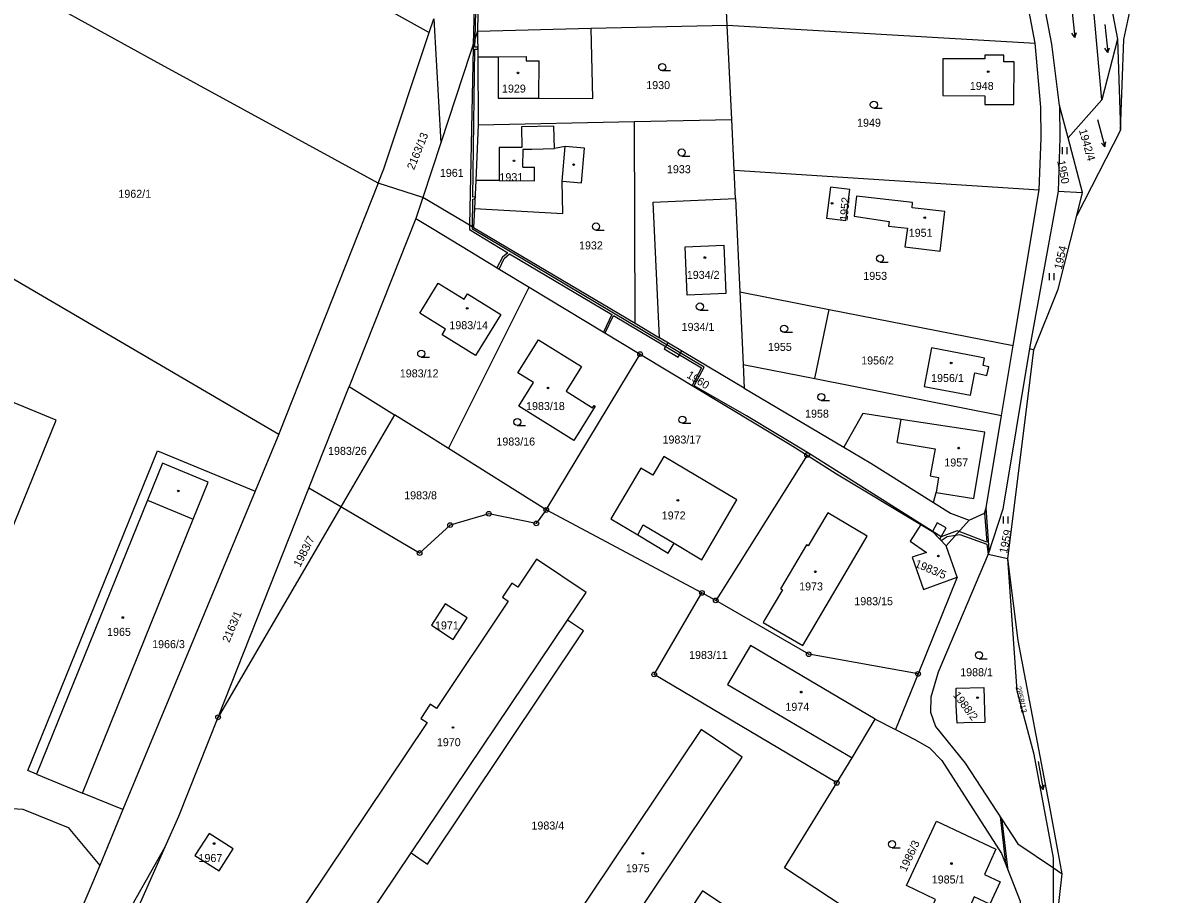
# Model space of a CAD drawing. Extents: x -562167 to -556918, y -1077891 to -1070763.
# Drawn here: x -560372.7 to -560130, y -1077028.4 to -1076843.2 of the extents above; entities that cross this region are included whole.
import ezdxf

# ---------------------------------------------------------------- set-up
doc = ezdxf.new("R2010")
doc.units = 0
for name, color, linetype in [('Hranice parcel', 7, 'Continuous'), ('Parcelní čísla', 7, 'Continuous'), ('Vnitřní kresba', 7, 'Continuous'), ('Věcná břemena k části', 7, 'Continuous'), ('Značky bodu BP', 7, 'Continuous'), ('Značky budov', 7, 'Continuous'), ('Značky kultur', 7, 'Continuous')]:
    doc.layers.add(name, color=color, linetype=linetype)

msp = doc.modelspace()

# ---------------------------------------------------------------- linework, layer by layer
at = {"layer": 'Hranice parcel'}
for p, q in [((-560358.76, -1076804.84), (-560286.39, -1076845.32)), ((-560138.79, -1076846.79), (-560130.01, -1076806.27)), ((-560157.61, -1076847.59), (-560163.26, -1076817.83)), ((-560275.77, -1076826.63), (-560276.1, -1076844.98)), ((-560223.06, -1076843.72), (-560223.82, -1076826.82)), ((-560143.58, -1076829.02), (-560140.13, -1076846.69)), ((-560286.39, -1076845.32), (-560285.41, -1076842.37)), ((-560285.41, -1076842.37), (-560283.95, -1076868.77)), ((-560276.1, -1076844.98), (-560251.98, -1076844.4)), ((-560251.98, -1076844.4), (-560223.06, -1076843.72)), ((-560223.06, -1076843.72), (-560157.61, -1076847.59)), ((-560222.12, -1076863.78), (-560223.06, -1076843.72)), ((-560276.1, -1076844.98), (-560283.95, -1076868.77)), ((-560276.1, -1076844.98), (-560276.06, -1076850.45)), ((-560140.13, -1076846.69), (-560143.47, -1076859.62)), ((-560140.13, -1076846.69), (-560139.49, -1076866.02)), ((-560139.49, -1076866.02), (-560138.79, -1076846.79)), ((-560276.06, -1076850.45), (-560275.96, -1076864.91)), ((-560150.64, -1076867.64), (-560152.43, -1076860.82)), ((-560150.64, -1076867.64), (-560143.47, -1076859.62)), ((-560242.76, -1076864.22), (-560222.12, -1076863.78)), ((-560221.61, -1076874.57), (-560222.12, -1076863.78)), ((-560275.96, -1076864.91), (-560276.49, -1076876.74)), ((-560275.96, -1076864.91), (-560242.76, -1076864.22)), ((-560242.66, -1076907.08), (-560242.76, -1076864.22)), ((-560139.49, -1076866.02), (-560148.79, -1076884.16)), ((-560283.95, -1076868.77), (-560287.76, -1076880.32)), ((-560147.57, -1076879.32), (-560150.64, -1076867.64)), ((-560221.61, -1076874.57), (-560156.75, -1076878.73)), ((-560221.32, -1076880.54), (-560221.61, -1076874.57)), ((-560287.76, -1076880.32), (-560297.22, -1076877.3)), ((-560276.49, -1076876.74), (-560276.76, -1076882.69)), ((-560404.42, -1076880.28), (-560318.34, -1076930.64)), ((-560287.76, -1076880.32), (-560289.24, -1076884.82)), ((-560276.95, -1076886.74), (-560287.76, -1076880.32)), ((-560221.32, -1076880.54), (-560220.39, -1076900.41)), ((-560162.28, -1076911.79), (-560156.75, -1076878.73)), ((-560152.76, -1076878.98), (-560158.84, -1076912.46)), ((-560152.76, -1076878.98), (-560147.57, -1076879.32)), ((-560148.79, -1076884.16), (-560147.57, -1076879.32)), ((-560276.76, -1076882.69), (-560276.95, -1076886.74)), ((-560289.24, -1076884.82), (-560303.38, -1076920.48)), ((-560276.95, -1076886.74), (-560242.66, -1076907.08)), ((-560282.32, -1076933.69), (-560265.13, -1076899.42)), ((-560265.13, -1076899.42), (-560241.57, -1076913.61)), ((-560220.39, -1076900.41), (-560201.37, -1076904.13)), ((-560220.39, -1076900.41), (-560219.67, -1076915.82)), ((-560204.45, -1076918.82), (-560201.37, -1076904.13)), ((-560201.37, -1076904.13), (-560162.28, -1076911.79)), ((-560242.66, -1076907.08), (-560237.45, -1076910.16)), ((-560219.44, -1076920.85), (-560237.45, -1076910.16)), ((-560164.75, -1076926.65), (-560162.28, -1076911.79)), ((-560158.84, -1076912.46), (-560157.89, -1076912.72)), ((-560261.53, -1076946.74), (-560241.57, -1076913.61)), ((-560159.06, -1076922), (-560157.89, -1076912.72)), ((-560219.67, -1076915.82), (-560219.44, -1076920.85)), ((-560219.67, -1076915.82), (-560204.45, -1076918.82)), ((-560204.45, -1076918.82), (-560164.75, -1076926.65)), ((-560311.95, -1076942.1), (-560303.38, -1076920.48)), ((-560303.38, -1076920.48), (-560293.79, -1076926.49)), ((-560219.44, -1076920.85), (-560198.26, -1076933.39)), ((-560163.47, -1076957.02), (-560159.06, -1076922)), ((-560293.79, -1076926.49), (-560305.19, -1076946.06)), ((-560318.34, -1076930.64), (-560323.37, -1076942.76)), ((-560261.53, -1076946.74), (-560282.32, -1076933.69)), ((-560323.37, -1076942.76), (-560351.46, -1077010.4)), ((-560331.26, -1076990.79), (-560311.95, -1076942.1)), ((-560305.19, -1076946.06), (-560311.95, -1076942.1)), ((-560305.19, -1076946.06), (-560331.26, -1076990.79)), ((-560228.44, -1076964.37), (-560261.53, -1076946.74)), ((-560176.56, -1076954.33), (-560171.65, -1076948.93)), ((-560174.22, -1076960.99), (-560176.56, -1076954.33)), ((-560167.65, -1076956.1), (-560163.47, -1076957.02)), ((-560161.27, -1076974.44), (-560163.47, -1076957.02)), ((-560174.22, -1076960.99), (-560182.51, -1076981.57)), ((-560225.49, -1076965.94), (-560228.44, -1076964.37)), ((-560154.36, -1077010.57), (-560161.27, -1076974.44)), ((-560182.51, -1076981.57), (-560187.28, -1076993.4)), ((-560339.58, -1077011.76), (-560331.26, -1076990.79)), ((-560196.51, -1076999.37), (-560191.62, -1076991.15)), ((-560191.62, -1076991.15), (-560187.28, -1076993.4)), ((-560199.79, -1077004.72), (-560196.51, -1076999.37)), ((-560369.83, -1077002.88), (-560360.08, -1077006.88)), ((-560351.46, -1077010.4), (-560360.08, -1077006.88)), ((-560351.46, -1077010.4), (-560356.38, -1077022.25)), ((-560342.5, -1077018.31), (-560339.58, -1077011.76)), ((-560151.86, -1077024.03), (-560154.36, -1077010.57)), ((-560365.26, -1077069.4), (-560342.5, -1077018.31)), ((-560153.76, -1077022.75), (-560151.86, -1077024.03))]:
    msp.add_line(p, q, dxfattribs=at)
for points in [[(-560152.43, -1076860.82), (-560154.11, -1076847.8), (-560159.77, -1076818.07), (-560165.49, -1076796.76)], [(-560143.47, -1076859.62), (-560146.38, -1076827.16), (-560146.45, -1076823.24)], [(-560297.22, -1076877.3), (-560344.8, -1076851.28), (-560374.15, -1076835.13), (-560376.33, -1076833.87)], [(-560276.06, -1076850.45), (-560271.74, -1076850.44), (-560271.72, -1076859.25), (-560263.06, -1076859.27), (-560251.63, -1076859.31), (-560251.98, -1076844.4)], [(-560297.22, -1076877.3), (-560296, -1076874.23), (-560286.39, -1076845.32)], [(-560156.75, -1076878.73), (-560156.36, -1076867.73), (-560156.45, -1076861.16), (-560157.61, -1076847.59)], [(-560164.32, -1076850.12), (-560168.35, -1076850.11), (-560168.36, -1076850.89), (-560177.23, -1076850.87), (-560177.25, -1076858.71), (-560168.35, -1076858.73), (-560168.35, -1076860.58), (-560162.13, -1076860.62), (-560162.11, -1076851.53), (-560164.32, -1076851.53), (-560164.32, -1076850.12)], [(-560152.43, -1076860.82), (-560152.39, -1076867.68), (-560152.76, -1076878.98)], [(-560276.76, -1076882.69), (-560257.96, -1076883.78), (-560258.11, -1076876.86), (-560254.05, -1076877.2), (-560253.37, -1076869.89), (-560257.49, -1076869.51), (-560259.79, -1076869.95), (-560259.89, -1076865.19), (-560266.75, -1076865.32), (-560266.72, -1076869.73), (-560271.53, -1076869.72), (-560271.55, -1076876.77), (-560276.49, -1076876.74)], [(-560297.22, -1076877.3), (-560318.25, -1076930.43), (-560318.34, -1076930.64)], [(-560201.13, -1076878.14), (-560201.99, -1076884.74), (-560197.88, -1076885.25), (-560197.04, -1076878.68), (-560201.13, -1076878.14)], [(-560237.45, -1076910.16), (-560238.8, -1076881.36), (-560221.32, -1076880.54)], [(-560183.71, -1076881.42), (-560195.59, -1076880.09), (-560196.06, -1076884.33), (-560188.67, -1076885.43), (-560188.82, -1076886.43), (-560184.79, -1076886.9), (-560185.33, -1076890.86), (-560177.84, -1076891.77), (-560176.83, -1076883.34), (-560183.78, -1076882.51), (-560183.71, -1076881.42)], [(-560289.24, -1076884.82), (-560285.69, -1076886.97), (-560277.76, -1076891.78), (-560271.04, -1076895.86), (-560265.13, -1076899.42)], [(-560157.89, -1076912.72), (-560152.72, -1076899.82), (-560148.79, -1076884.16)], [(-560223.37, -1076900.77), (-560231.57, -1076901.08), (-560232.01, -1076890.8), (-560223.78, -1076890.46), (-560223.37, -1076900.77)], [(-560276.53, -1076913.92), (-560283.62, -1076909.53), (-560282.91, -1076908.35), (-560288.38, -1076904.94), (-560284.45, -1076898.56), (-560278.93, -1076901.98), (-560278.22, -1076900.84), (-560271.14, -1076905.23), (-560276.53, -1076913.92)], [(-560251.68, -1076925.02), (-560251.37, -1076924.53), (-560251.11, -1076924.7), (-560255.67, -1076931.98), (-560267.35, -1076924.69), (-560264.21, -1076919.65), (-560267.53, -1076917.57), (-560263.16, -1076910.56), (-560254.02, -1076916.23), (-560257.3, -1076921.49), (-560251.68, -1076925.02)], [(-560168.38, -1076914.45), (-560169.76, -1076914.18), (-560179.63, -1076912.26), (-560181.24, -1076920.48), (-560171.37, -1076922.32), (-560170.44, -1076917.63), (-560169.07, -1076917.9), (-560167.89, -1076918.14), (-560167.51, -1076916.31), (-560168.7, -1076916.07), (-560168.38, -1076914.45)], [(-560158.84, -1076912.46), (-560164.52, -1076946.6), (-560167.65, -1076956.1)], [(-560241.57, -1076913.61), (-560209.7, -1076932.8), (-560206.09, -1076935.09)], [(-560376.98, -1076922.98), (-560407.33, -1076997.49), (-560395.97, -1077002.18), (-560365.66, -1076927.66), (-560376.98, -1076922.98)], [(-560282.32, -1076933.69), (-560288.19, -1076930), (-560293.79, -1076926.49)], [(-560179.24, -1076945.18), (-560178.69, -1076943.01), (-560170.69, -1076944.28), (-560168.36, -1076930.23), (-560186.11, -1076927.5), (-560194.25, -1076926.24), (-560198.26, -1076933.39)], [(-560171.65, -1076948.93), (-560168.43, -1076947.44), (-560168.01, -1076946.26), (-560164.75, -1076926.65)], [(-560369.83, -1077002.88), (-560371.7, -1077002.11), (-560344.14, -1076934.2), (-560323.37, -1076942.76)], [(-560198.26, -1076933.39), (-560192.56, -1076936.77), (-560179.24, -1076945.18)], [(-560360.08, -1077006.88), (-560336.56, -1076948.66), (-560333.38, -1076940.8), (-560343.04, -1076936.81), (-560346.22, -1076944.64), (-560369.83, -1077002.88)], [(-560241.39, -1076937.83), (-560247.8, -1076948.61), (-560242.07, -1076952.03), (-560235.6, -1076955.88), (-560234.37, -1076953.81), (-560228.45, -1076957.35), (-560221, -1076944.6), (-560236.51, -1076935.39), (-560238.86, -1076939.33), (-560241.39, -1076937.83)], [(-560206.09, -1076935.09), (-560207.26, -1076936.99), (-560224.5, -1076964.38), (-560225.49, -1076965.94)], [(-560206.09, -1076935.09), (-560199.82, -1076939.08), (-560181.95, -1076949.79)], [(-560261.53, -1076946.74), (-560263.63, -1076949.59), (-560273.72, -1076947.54), (-560281.95, -1076949.95), (-560288.43, -1076955.88), (-560305.19, -1076946.06)], [(-560179.24, -1076945.18), (-560175.65, -1076947.44), (-560171.65, -1076948.93)], [(-560215.05, -1076970.03), (-560215.41, -1076970.63), (-560206.97, -1076975.53), (-560193.32, -1076952.27), (-560201.72, -1076947.32), (-560205.86, -1076954.38), (-560206.25, -1076954.15), (-560211.74, -1076963.5), (-560211.35, -1076963.73), (-560215.05, -1076970.03)], [(-560181.95, -1076949.79), (-560184.16, -1076953.34), (-560180.69, -1076955.74), (-560183.79, -1076956.79), (-560181.39, -1076963.63), (-560174.22, -1076960.99)], [(-560181.95, -1076949.79), (-560179.45, -1076951.29), (-560176.56, -1076954.33)], [(-560167.65, -1076956.1), (-560178.21, -1076981.17), (-560179.78, -1076986.54), (-560179.87, -1076989.69), (-560178.79, -1076992.75), (-560172.51, -1077000.5), (-560161.31, -1077017.69), (-560153.76, -1077022.75)], [(-560253.06, -1076964.3), (-560263.6, -1076957.2), (-560267.57, -1076963.12), (-560268.82, -1076962.29), (-560270.82, -1076965.28), (-560269.58, -1076966.11), (-560284.86, -1076988.9), (-560286.16, -1076988.02), (-560288.15, -1076991.05), (-560286.85, -1076991.87), (-560316.67, -1077036.36), (-560306.13, -1077043.3), (-560290.21, -1077019.59), (-560286.77, -1077021.96), (-560253.61, -1076972.43), (-560257, -1076970.16), (-560253.06, -1076964.3)], [(-560153.76, -1077022.75), (-560153.77, -1077020.64), (-560157.84, -1076998.71), (-560161.44, -1076985.13), (-560163.47, -1076957.02)], [(-560199.79, -1077004.72), (-560238.58, -1076981.68), (-560228.44, -1076964.37)], [(-560182.51, -1076981.57), (-560205.75, -1076977.4), (-560225.49, -1076965.94)], [(-560282.97, -1076966.68), (-560285.92, -1076971.22), (-560281.31, -1076974.24), (-560278.31, -1076969.65), (-560282.97, -1076966.68)], [(-560191.62, -1076991.15), (-560218.14, -1076975.55), (-560222.98, -1076983.79), (-560196.51, -1076999.37)], [(-560168.34, -1076991.87), (-560172.78, -1076991.97), (-560174.21, -1076992.03), (-560174.39, -1076988.29), (-560174.45, -1076984.62), (-560168.52, -1076984.47), (-560168.34, -1076991.87)], [(-560219.92, -1076999.22), (-560228.6, -1076993.37), (-560261.43, -1077042.32), (-560252.66, -1077048.23), (-560219.92, -1076999.22)], [(-560187.28, -1076993.4), (-560183.21, -1076995.5), (-560180.06, -1076997.25), (-560177.46, -1076999.96), (-560164.79, -1077019.71), (-560160.81, -1077029.84), (-560161.95, -1077050.53)], [(-560161.95, -1077050.53), (-560175.96, -1077045.8), (-560210.86, -1077022.78), (-560199.79, -1077004.72)], [(-560375.02, -1077010.14), (-560372.73, -1077010.32), (-560363.14, -1077014.22), (-560356.38, -1077022.25)], [(-560165.09, -1077025.71), (-560167.28, -1077030.45), (-560170.57, -1077028.95), (-560173.53, -1077035.43), (-560175, -1077034.76), (-560176.62, -1077035.08), (-560178.24, -1077034.22), (-560178.94, -1077032.72), (-560180.04, -1077032.21), (-560178.79, -1077029.48), (-560184.98, -1077026.51), (-560178.57, -1077012.84), (-560165.96, -1077018.79), (-560168.41, -1077024.19), (-560165.09, -1077025.71)], [(-560328.04, -1077018.75), (-560333.17, -1077015.46), (-560336.18, -1077020.14), (-560331.05, -1077023.4), (-560328.04, -1077018.75)], [(-560393.7, -1077108.68), (-560378.79, -1077082.83), (-560371.26, -1077069.21), (-560369.73, -1077066.57), (-560357.74, -1077045.23), (-560342.5, -1077018.31)], [(-560356.38, -1077022.25), (-560358.68, -1077027.79), (-560380.96, -1077079.72)], [(-560160.99, -1077155.03), (-560161.61, -1077141.5), (-560161.97, -1077130.79), (-560160.9, -1077101.8), (-560158.8, -1077080.3), (-560153.74, -1077030.09), (-560153.76, -1077022.75)], [(-560157.7, -1077074.67), (-560154.26, -1077044.8), (-560151.86, -1077024.03)], [(-560178.19, -1077061.35), (-560228.3, -1077027.65), (-560236.61, -1077040.16), (-560186.49, -1077073.87), (-560178.19, -1077061.35)]]:
    msp.add_lwpolyline(points, dxfattribs=at)
at = {"layer": 'Vnitřní kresba'}
for p, q in [((-560271.74, -1076850.44), (-560265.77, -1076850.42)), ((-560265.77, -1076850.42), (-560265.77, -1076851.32)), ((-560265.77, -1076851.32), (-560263.04, -1076851.33)), ((-560263.06, -1076859.27), (-560263.04, -1076851.33)), ((-560266.47, -1076873.88), (-560266.42, -1076870.11)), ((-560266.42, -1076870.11), (-560264.6, -1076870.06)), ((-560264.6, -1076870.06), (-560259.79, -1076869.95)), ((-560258.11, -1076876.86), (-560257.49, -1076869.51)), ((-560266.47, -1076873.88), (-560263.99, -1076873.93)), ((-560264.02, -1076876.82), (-560263.99, -1076873.93)), ((-560271.55, -1076876.77), (-560264.02, -1076876.82)), ((-560186.97, -1076932.39), (-560186.11, -1076927.5)), ((-560186.97, -1076932.39), (-560178.91, -1076933.76)), ((-560178.91, -1076933.76), (-560179.96, -1076939.51)), ((-560179.96, -1076939.51), (-560178.19, -1076939.85)), ((-560178.19, -1076939.85), (-560178.69, -1076943.01)), ((-560346.22, -1076944.64), (-560336.56, -1076948.66)), ((-560242.07, -1076952.03), (-560240.92, -1076949.9)), ((-560240.92, -1076949.9), (-560234.37, -1076953.81)), ((-560290.21, -1077019.59), (-560257, -1076970.16))]:
    msp.add_line(p, q, dxfattribs=at)
at = {"layer": 'Věcná břemena k části'}
for points in [[(-560277.05, -1076847.86), (-560276.62, -1076846.55), (-560276.18, -1076829.06), (-560275.81, -1076829.08), (-560275.81, -1076828.67), (-560276.26, -1076828.65), (-560276.24, -1076826.64), (-560276.66, -1076826.64), (-560277.58, -1076828.8), (-560284.57, -1076829.65), (-560284.57, -1076830.05), (-560276.58, -1076829.08)], [(-560277.21, -1076886.59), (-560277.11, -1076880.71), (-560276.67, -1076880.64), (-560276.65, -1076880.24), (-560277.11, -1076880.31), (-560276.67, -1076848.84), (-560276.07, -1076848.82), (-560276.07, -1076848.42), (-560276.66, -1076848.43), (-560276.62, -1076846.55), (-560277.05, -1076847.86), (-560277.07, -1076848.63), (-560277.82, -1076886.23)], [(-560277.21, -1076886.59), (-560277.82, -1076886.23), (-560277.84, -1076887.18), (-560269.67, -1076892.1), (-560270.79, -1076893.05), (-560272.03, -1076895.26), (-560271.52, -1076895.57), (-560270.47, -1076893.29), (-560269.32, -1076892.32), (-560247.61, -1076905.2), (-560249.35, -1076908.93), (-560249, -1076909.13), (-560247.26, -1076905.4), (-560228.5, -1076916.54), (-560230.51, -1076920.27), (-560209.7, -1076932.8), (-560206.09, -1076935.09), (-560199.82, -1076939.08), (-560181.95, -1076949.79), (-560179.45, -1076951.29), (-560177.62, -1076953.22), (-560176.35, -1076952.39), (-560174.54, -1076952.1), (-560173.8, -1076951.29), (-560174.18, -1076951.14), (-560177.61, -1076952.43), (-560205.77, -1076934.69), (-560218.94, -1076926.72), (-560230.09, -1076920.33), (-560227.96, -1076916.4), (-560247.26, -1076904.94), (-560277.22, -1076887.08)], [(-560232.74, -1076912.96), (-560235.69, -1076911.21), (-560236.45, -1076912.48), (-560233.52, -1076914.25)], [(-560173.8, -1076951.29), (-560174.54, -1076952.1), (-560173.65, -1076951.97), (-560167.87, -1076954.02), (-560167.65, -1076956.1), (-560167.37, -1076955.26), (-560168.01, -1076946.26), (-560168.43, -1076947.44), (-560167.9, -1076953.58)], [(-560178.42, -1076949.46), (-560179.45, -1076951.29), (-560177.9, -1076952.92), (-560176.55, -1076950.5)], [(-560163.94, -1077021.86), (-560163.37, -1077023.32), (-560164.61, -1077012.63), (-560165.1, -1077011.87)]]:
    msp.add_lwpolyline(points, close=True, dxfattribs=at)
at = {"layer": 'Značky bodu BP'}
for centre, radius in [((-560241.57, -1076913.61), 0.5), ((-560241.57, -1076913.61), 0.0303), ((-560206.09, -1076935.09), 0.5), ((-560206.09, -1076935.09), 0.0303), ((-560261.53, -1076946.74), 0.5), ((-560273.72, -1076947.54), 0.5), ((-560273.72, -1076947.54), 0.0303), ((-560261.53, -1076946.74), 0.0303), ((-560281.95, -1076949.95), 0.5), ((-560281.95, -1076949.95), 0.0303), ((-560263.63, -1076949.59), 0.5), ((-560263.63, -1076949.59), 0.0303), ((-560288.43, -1076955.88), 0.5), ((-560288.43, -1076955.88), 0.0303), ((-560228.44, -1076964.37), 0.5), ((-560228.44, -1076964.37), 0.0303), ((-560225.49, -1076965.94), 0.5), ((-560225.49, -1076965.94), 0.0303), ((-560205.75, -1076977.4), 0.5), ((-560205.75, -1076977.4), 0.0303), ((-560238.58, -1076981.68), 0.5), ((-560238.58, -1076981.68), 0.0303), ((-560182.51, -1076981.57), 0.5), ((-560182.51, -1076981.57), 0.0303), ((-560331.26, -1076990.79), 0.5), ((-560331.26, -1076990.79), 0.0303), ((-560199.79, -1077004.72), 0.5), ((-560199.79, -1077004.72), 0.0303)]:
    msp.add_circle(centre, radius, dxfattribs=at)
at = {"layer": 'Značky budov'}
for centre in [(-560267.53, -1076853.87), (-560167.6, -1076853.62), (-560268.38, -1076872.56), (-560255.7, -1076873.37), (-560200.77, -1076881.59), (-560181.09, -1076884.62), (-560227.81, -1076893.11), (-560278.32, -1076903.9), (-560175.47, -1076915.51), (-560261.13, -1076920.81), (-560173.88, -1076933.6), (-560339.7, -1076942.69), (-560233.55, -1076944.69), (-560178.19, -1076956.53), (-560204.35, -1076959.87), (-560351.49, -1076969.59), (-560207.35, -1076985.44), (-560169.87, -1076986.63), (-560281.34, -1076992.95), (-560332.09, -1077017.61), (-560240.99, -1077019.7), (-560175.41, -1077021.85)]:
    msp.add_circle(centre, 0.175, dxfattribs=at)
at = {"layer": 'Značky kultur'}
for p, q in [((-560149.86, -1076840.37), (-560149.23, -1076846.34)), ((-560142.85, -1076843.6), (-560142.22, -1076849.57)), ((-560149.23, -1076846.34), (-560149.83, -1076845.42)), ((-560149.23, -1076846.34), (-560148.84, -1076845.32)), ((-560142.22, -1076849.57), (-560142.82, -1076848.65)), ((-560142.22, -1076849.57), (-560141.83, -1076848.55)), ((-560236.87, -1076853.4), (-560235.12, -1076853.4)), ((-560191.91, -1076861.38), (-560190.16, -1076861.38)), ((-560144.38, -1076863.81), (-560142.83, -1076869.61)), ((-560142.83, -1076869.61), (-560143.57, -1076868.79)), ((-560142.83, -1076869.61), (-560142.6, -1076868.53)), ((-560151.82, -1076871.14), (-560151.82, -1076869.64)), ((-560150.82, -1076871.14), (-560150.82, -1076869.64)), ((-560232.74, -1076871.54), (-560230.99, -1076871.54)), ((-560250.95, -1076887.26), (-560249.2, -1076887.26)), ((-560190.59, -1076894.06), (-560188.84, -1076894.06)), ((-560154.57, -1076897.91), (-560154.57, -1076896.41)), ((-560153.57, -1076897.91), (-560153.57, -1076896.41)), ((-560228.88, -1076904.26), (-560227.13, -1076904.26)), ((-560210.97, -1076908.99), (-560209.22, -1076908.99)), ((-560288.09, -1076914.27), (-560286.34, -1076914.27)), ((-560203.08, -1076923.49), (-560201.33, -1076923.49)), ((-560267.67, -1076928.79), (-560265.92, -1076928.79)), ((-560232.58, -1076928.31), (-560230.83, -1076928.31)), ((-560164.37, -1076949.59), (-560164.37, -1076948.09)), ((-560163.37, -1076949.59), (-560163.37, -1076948.09)), ((-560169.56, -1076978.35), (-560167.81, -1076978.35)), ((-560157.01, -1077000.18), (-560155.96, -1077006.09)), ((-560155.96, -1077006.09), (-560156.63, -1077005.22)), ((-560155.96, -1077006.09), (-560155.64, -1077005.04)), ((-560188.04, -1077018.49), (-560186.29, -1077018.49))]:
    msp.add_line(p, q, dxfattribs=at)
for centre in [(-560236.87, -1076852.65), (-560191.91, -1076860.63), (-560232.74, -1076870.79), (-560250.95, -1076886.51), (-560190.59, -1076893.31), (-560228.88, -1076903.51), (-560210.97, -1076908.24), (-560288.09, -1076913.52), (-560203.08, -1076922.74), (-560232.58, -1076927.56), (-560267.67, -1076928.04), (-560169.56, -1076977.6), (-560188.04, -1077017.74)]:
    msp.add_circle(centre, 0.75, dxfattribs=at)

# ---------------------------------------------------------------- texts
at = {"layer": 'Parcelní čísla'}
for s, p in [('1929', (-560270.92, -1076858.06)), ('1930', (-560240.27, -1076857.32)), ('1948', (-560171.51, -1076857.5)), ('1949', (-560195.47, -1076865.31)), ('1933', (-560235.87, -1076875.19)), ('1961', (-560284.12, -1076875.97)), ('1931', (-560271.46, -1076876.88)), ('1962/1', (-560352.43, -1076880.41)), ('1951', (-560184.49, -1076888.7)), ('1932', (-560254.55, -1076891.38)), ('1934/2', (-560231.65, -1076897.64)), ('1953', (-560194.15, -1076897.85)), ('1983/14', (-560282.1, -1076908.33)), ('1934/1', (-560232.75, -1076908.69)), ('1955', (-560214.41, -1076912.93)), ('1956/2', (-560194.6, -1076915.82)), ('1983/12', (-560292.63, -1076918.57)), ('1956/1', (-560179.74, -1076919.55)), ('1983/18', (-560265.8, -1076925.51)), ('1958', (-560206.52, -1076927.12)), ('1983/16', (-560272.11, -1076933.05)), ('1983/17', (-560236.81, -1076932.62)), ('1983/26', (-560307.88, -1076935.03)), ('1957', (-560176.93, -1076937.5)), ('1983/8', (-560291.7, -1076944.47)), ('1972', (-560236.97, -1076948.75)), ('1973', (-560207.78, -1076963.83)), ('1983/15', (-560196.06, -1076966.97)), ('1971', (-560285.16, -1076972.11)), ('1965', (-560354.84, -1076973.48)), ('1966/3', (-560345.26, -1076976.09)), ('1983/11', (-560231.17, -1076978.39)), ('1988/1', (-560173.56, -1076982.05)), ('1974', (-560210.7, -1076989.41)), ('1970', (-560284.76, -1076996.92)), ('1983/4', (-560264.66, -1077014.63)), ('1967', (-560335.41, -1077021.53)), ('1975', (-560244.61, -1077023.7)), ('1985/1', (-560179.6, -1077026.09))]:
    msp.add_text(s, height=1.7, dxfattribs=at).set_placement(p)
for s, height, rotation, p in [('1942/4', 1.7, 286, (-560148.35, -1076866.06)), ('2163/13', 1.7, 68, (-560289.62, -1076874.6)), ('1950', 1.7, 281, (-560152.96, -1076872.6)), ('1952', 1.7, 85, (-560197.49, -1076885.39)), ('1954', 1.7, 77, (-560151.99, -1076895.75)), ('1960', 1.7, 328, (-560231.83, -1076918.49)), ('1959', 1.7, 78, (-560163.63, -1076956.08)), ('1983/7', 1.7, 63, (-560313.82, -1076959.01)), ('1983/5', 1.7, 337, (-560183.35, -1076958.75)), ('2163/1', 1.7, 67, (-560328.88, -1076975.05)), ('2858/13', 1.2, 283, (-560161.82, -1076984.32)), ('1988/2', 1.7, 307, (-560175.19, -1076986.11)), ('1986/3', 1.7, 65, (-560185.05, -1077023.73))]:
    msp.add_text(s, height=height, rotation=rotation, dxfattribs=at).set_placement(p)

doc.saveas('drawing.dxf')
